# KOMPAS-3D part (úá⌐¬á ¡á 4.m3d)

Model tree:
1. Эскиз:1
2. Операция выдавливания:1
     Расстояние 1 = 2
3. Эскиз:4
4. Отверстие:2
5. Условное изображение резьбы:2
     Длина резьбы = 2; Шаг резьбы = 1.5; Номинальный диаметр резьбы = 5.6238
6. Скругление:2
     Радиус = 0.1

Referenced files in C:\Program Files\ASCON\KOMPAS-3D V13 Home\Sys\: holelib.lfr
Referenced files in C:\Program Files\ASCON\KOMPAS-3D V12\Sys\: holelib.lfr
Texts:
  гайка на 4
  Отверстие 01
  (вариант 1)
